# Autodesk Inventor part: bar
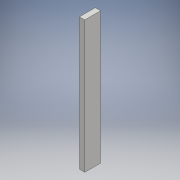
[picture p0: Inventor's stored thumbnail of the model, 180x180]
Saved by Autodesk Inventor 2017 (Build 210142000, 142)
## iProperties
Created: 2017-04
Part Number: bar
Material: Generic
Document SubType Name: Modeling
Designer: s4321966
Density: 1 g/cm^3
Appearance: Default
Author: s4321966
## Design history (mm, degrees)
sketch "Sketch1"
  geometry: L1 (0, 0)-(6, 0); L2 (6, 0)-(6, -50); L3 (6, -50)-(0, -50); L4 (0, -50)-(0, 0)
  constraints: 8 end point, 2 parallel, 1 horizontal, 1 perpendicular
  dimensions: "d0" = 6 distance of L2.end L3.end; "d1" = 50 distance of L1.end L2.end
extrude "Extrusion1" new body sketch "Sketch1" distance "d2" = 2; taper "d3" = 0 deg
body "Solid1"
